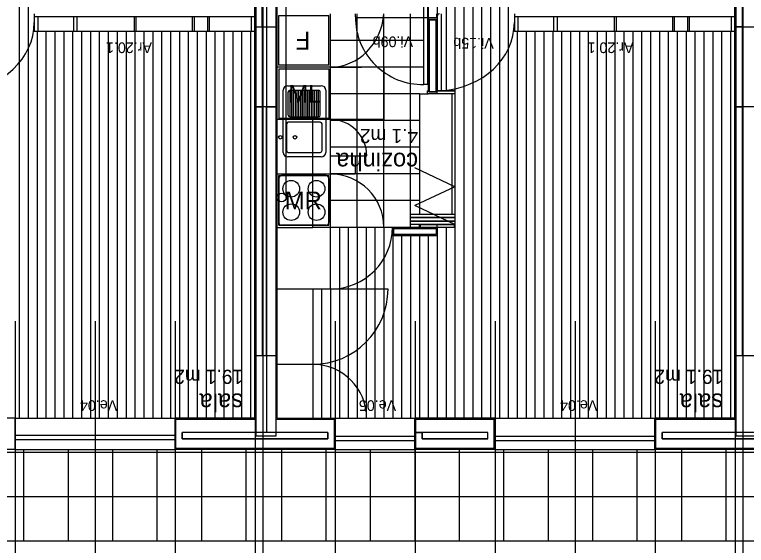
# Model space of a CAD drawing. Extents: x 1248 to 1356, y -443 to -224.
# Drawn here: x 1326.49 to 1334.72, y -248 to -242.03 of the extents above; entities that cross this region are included whole.
import ezdxf

# ---------------------------------------------------------------- set-up
doc = ezdxf.new("R2010")
doc.units = 0
for name, color, linetype in [('corte', 7, 'Continuous'), ('estereoctomias', 7, 'Continuous'), ('Level 1', 7, 'Continuous'), ('Level 10', 7, 'Continuous'), ('Level 11', 7, 'Continuous'), ('Level 13', 7, 'Continuous'), ('Level 2', 7, 'Continuous'), ('Level 3', 7, 'Continuous'), ('Level 4', 7, 'Continuous'), ('Level 40', 7, 'Continuous'), ('Level 60', 7, 'Continuous'), ('mob-fixo', 7, 'Continuous'), ('revestimentos', 7, 'Continuous'), ('vermelhos-cont', 7, 'Continuous'), ('vermelhos-tracej', 7, 'Continuous')]:
    doc.layers.add(name, color=color, linetype=linetype)

msp = doc.modelspace()

# ---------------------------------------------------------------- linework, layer by layer
at = {"layer": 'corte'}
for p, q in [((1331.1475, -242.892), (1331.1475, -242.902)), ((1331.2375, -242.892), (1331.2375, -242.924)), ((1328.304, -246.584), (1329.2018, -246.584)), ((1333.7025, -246.584), (1334.6025, -246.584)), ((1330.0125, -246.734), (1328.374, -246.734)), ((1331.8125, -246.734), (1331.0725, -246.734)), ((1335.414, -246.734), (1333.7725, -246.734)), ((1330.0125, -246.804), (1328.374, -246.804)), ((1331.8125, -246.804), (1331.0725, -246.804)), ((1335.414, -246.804), (1333.7725, -246.804)), ((1330.0825, -246.914), (1328.304, -246.914)), ((1331.8825, -246.914), (1331.0025, -246.914)), ((1335.484, -246.914), (1333.7025, -246.914))]:
    msp.add_line(p, q, dxfattribs=at)
for points in [[(1329.4318, -243.0713), (1329.2018, -243.0713), (1329.2018, -242.1713), (1329.4318, -242.1713)], [(1334.8325, -243.0713), (1334.6025, -243.0713), (1334.6025, -242.1713), (1334.8325, -242.1713)], [(1329.4318, -245.8713), (1329.2018, -245.8713), (1329.2018, -246.7713), (1329.4318, -246.7713)], [(1334.8325, -245.8713), (1334.6025, -245.8713), (1334.6025, -246.7713), (1334.8325, -246.7713)]]:
    msp.add_lwpolyline(points, close=True, dxfattribs=at)
at = {"layer": 'estereoctomias'}
for points in [[(1326.0268, -240.354), (1326.0268, -240.424), (1329.2018, -240.424), (1329.2018, -242.1713), (1329.2718, -242.1713), (1329.2718, -240.354), (1326.0268, -240.354)], [(1329.3225, -242.1713), (1329.4318, -242.1713), (1329.4325, -240.754), (1330.3525, -240.754), (1330.3525, -241.264), (1330.4875, -241.264), (1330.4875, -240.304), (1330.4325, -240.304), (1330.4325, -240.604), (1329.4325, -240.604), (1329.4325, -240.304), (1329.3225, -240.304)], [(1334.6725, -240.354), (1334.6725, -242.1713), (1334.6025, -242.1713), (1334.6025, -240.424), (1331.4125, -240.424), (1331.4125, -240.354)], [(1331.2275, -242.094), (1331.2275, -242.902), (1331.1575, -242.902), (1331.1575, -242.094)], [(1331.4425, -242.892), (1331.4425, -242.924), (1331.1325, -242.924), (1331.1325, -242.892), (1331.1475, -242.892), (1331.1475, -242.902), (1331.2375, -242.902), (1331.2375, -242.892), (1331.4425, -242.892)], [(1329.2718, -245.8713), (1329.2018, -245.8713), (1329.2018, -243.0713), (1329.2718, -243.0713)], [(1329.4318, -245.8713), (1329.3225, -245.8713), (1329.3225, -243.0713), (1329.4325, -243.0713), (1329.4325, -245.8713)], [(1334.6725, -245.8713), (1334.6025, -245.8713), (1334.6025, -243.0713), (1334.6725, -243.0713)], [(1331.2325, -244.4379), (1331.2325, -244.5079), (1330.7525, -244.5079), (1330.7525, -244.4379)], [(1331.4425, -244.3959), (1331.4425, -244.4279), (1331.0425, -244.4279), (1331.0425, -244.3959)], [(1329.4325, -246.584), (1330.0825, -246.584), (1330.0825, -246.914), (1328.304, -246.914), (1328.304, -246.584), (1329.2018, -246.584), (1329.2018, -246.734), (1328.374, -246.734), (1328.374, -246.804), (1330.0125, -246.804), (1330.0125, -246.734), (1329.4318, -246.734)], [(1331.8825, -246.584), (1331.8825, -246.914), (1331.0025, -246.914), (1331.0025, -246.734), (1331.0725, -246.734), (1331.0725, -246.804), (1331.8125, -246.804), (1331.8125, -246.734), (1331.0025, -246.734), (1331.0025, -246.584)], [(1334.8333, -246.584), (1335.484, -246.584), (1335.484, -246.914), (1333.7025, -246.914), (1333.7025, -246.584), (1334.6025, -246.584), (1334.6025, -246.734), (1333.7725, -246.734), (1333.7725, -246.804), (1335.414, -246.804), (1335.414, -246.734), (1334.8325, -246.734)]]:
    msp.add_lwpolyline(points, close=True, dxfattribs=at)
at = {"layer": 'Level 1'}
for p, q in [((1329.2718, -240.354), (1329.2718, -245.8713)), ((1329.3225, -240.304), (1329.3225, -246.734)), ((1334.6725, -240.354), (1334.6725, -245.8713)), ((1329.2018, -240.424), (1329.2018, -246.584)), ((1329.2018, -246.584), (1329.2018, -240.424)), ((1334.6025, -240.424), (1334.6025, -246.584)), ((1334.6025, -246.584), (1334.6025, -240.424)), ((1329.4325, -246.584), (1329.4325, -241.934)), ((1331.1575, -242.902), (1331.1575, -242.094)), ((1331.1575, -242.094), (1331.2275, -242.094)), ((1331.2275, -242.094), (1331.2275, -242.902)), ((1331.1475, -242.892), (1331.1325, -242.892)), ((1331.1325, -242.924), (1331.1325, -242.892)), ((1331.1475, -242.902), (1331.2375, -242.902)), ((1331.4425, -242.892), (1331.2375, -242.892)), ((1331.4425, -242.892), (1331.4425, -242.924)), ((1331.4425, -242.924), (1331.1325, -242.924)), ((1331.2325, -244.4379), (1330.7525, -244.4379)), ((1330.7525, -244.4379), (1330.7525, -244.5079)), ((1331.0425, -244.3959), (1331.0425, -244.424)), ((1331.4425, -244.3959), (1331.0425, -244.3959)), ((1331.0425, -244.3959), (1331.0425, -244.4279)), ((1331.0525, -244.3959), (1331.0525, -244.4279)), ((1331.2325, -244.4379), (1331.2325, -244.5079)), ((1331.2425, -244.4279), (1331.2425, -244.3959)), ((1331.4425, -244.4279), (1331.2425, -244.4279)), ((1331.4325, -244.3959), (1331.4325, -244.4279)), ((1331.4425, -244.3959), (1331.4425, -244.4279)), ((1330.7525, -244.5079), (1331.2325, -244.5079)), ((1328.304, -246.914), (1328.304, -246.584)), ((1329.4325, -246.584), (1330.0825, -246.584)), ((1330.0825, -246.584), (1330.0825, -246.914)), ((1331.8825, -246.584), (1331.0025, -246.584)), ((1331.0025, -246.914), (1331.0025, -246.584)), ((1331.8825, -246.914), (1331.8825, -246.584)), ((1333.7025, -246.914), (1333.7025, -246.584)), ((1328.374, -246.804), (1328.374, -246.734)), ((1330.0125, -246.734), (1330.0125, -246.804)), ((1331.0725, -246.804), (1331.0725, -246.734)), ((1331.8125, -246.804), (1331.8125, -246.734)), ((1333.7725, -246.804), (1333.7725, -246.734))]:
    msp.add_line(p, q, dxfattribs=at)
at = {"layer": 'Level 10'}
for p, q in [((1331.1425, -240.424), (1331.1425, -242.892)), ((1331.2425, -240.424), (1331.2425, -242.892)), ((1331.4425, -240.434), (1331.4425, -242.892)), ((1331.5425, -240.434), (1331.5425, -246.574)), ((1331.6425, -240.434), (1331.6425, -246.574)), ((1331.7425, -240.434), (1331.7425, -246.574)), ((1331.8425, -240.434), (1331.8425, -246.574)), ((1331.9425, -240.434), (1331.9425, -246.574)), ((1332.0425, -240.434), (1332.0425, -246.574)), ((1326.5418, -240.439), (1326.5418, -246.574)), ((1326.6418, -240.439), (1326.6418, -246.574)), ((1331.3425, -240.439), (1331.3425, -242.892)), ((1330.3425, -244.428), (1330.3425, -242.024)), ((1330.6425, -244.428), (1330.6425, -242.024)), ((1330.9425, -244.428), (1330.9425, -242.024)), ((1326.7418, -242.224), (1326.7418, -246.574)), ((1326.8418, -242.224), (1326.8418, -246.574)), ((1326.9418, -242.224), (1326.9418, -246.574)), ((1327.0418, -242.224), (1327.0418, -246.574)), ((1327.1418, -242.224), (1327.1418, -246.574)), ((1327.2418, -242.224), (1327.2418, -246.574)), ((1327.3418, -242.224), (1327.3418, -246.574)), ((1327.4418, -242.224), (1327.4418, -246.574)), ((1327.5418, -242.224), (1327.5418, -246.574)), ((1327.6418, -242.224), (1327.6418, -246.574)), ((1327.7418, -242.224), (1327.7418, -246.574)), ((1327.8418, -242.224), (1327.8418, -246.574)), ((1327.9418, -242.224), (1327.9418, -246.574)), ((1328.0418, -242.224), (1328.0418, -246.574)), ((1328.1418, -242.224), (1328.1418, -246.574)), ((1328.2418, -242.224), (1328.2418, -246.574)), ((1328.3418, -242.224), (1328.3418, -246.574)), ((1328.4418, -242.224), (1328.4418, -246.574)), ((1328.5418, -242.224), (1328.5418, -246.574)), ((1328.6418, -242.224), (1328.6418, -246.574)), ((1328.7418, -242.224), (1328.7418, -246.574)), ((1328.8418, -242.224), (1328.8418, -246.574)), ((1328.9418, -242.224), (1328.9418, -246.574)), ((1329.0418, -242.224), (1329.0418, -246.574)), ((1329.1418, -242.224), (1329.1418, -246.574)), ((1332.1425, -242.224), (1332.1425, -246.574)), ((1332.2425, -242.224), (1332.2425, -246.574)), ((1332.3425, -242.224), (1332.3425, -246.574)), ((1332.4425, -242.224), (1332.4425, -246.574)), ((1332.5425, -242.224), (1332.5425, -246.574)), ((1332.6425, -242.224), (1332.6425, -246.574)), ((1332.7425, -242.224), (1332.7425, -246.574)), ((1332.8425, -242.224), (1332.8425, -246.574)), ((1332.9425, -242.224), (1332.9425, -246.574)), ((1333.0425, -242.224), (1333.0425, -246.574)), ((1333.1425, -242.224), (1333.1425, -246.574)), ((1333.2425, -242.224), (1333.2425, -246.574)), ((1333.3425, -242.224), (1333.3425, -246.574)), ((1333.4425, -242.224), (1333.4425, -246.574)), ((1333.5425, -242.224), (1333.5425, -246.574)), ((1333.6425, -242.224), (1333.6425, -246.574)), ((1333.7425, -242.224), (1333.7425, -246.574)), ((1333.8425, -242.224), (1333.8425, -246.574)), ((1333.9425, -242.224), (1333.9425, -246.574)), ((1334.0425, -242.224), (1334.0425, -246.574)), ((1334.1425, -242.224), (1334.1425, -246.574)), ((1334.2425, -242.224), (1334.2425, -246.574)), ((1334.3425, -242.224), (1334.3425, -246.574)), ((1334.4425, -242.224), (1334.4425, -246.574)), ((1334.5425, -242.224), (1334.5425, -246.574)), ((1331.0925, -242.324), (1330.0425, -242.324)), ((1331.0925, -242.624), (1330.0425, -242.624)), ((1331.0925, -242.624), (1330.0425, -242.624)), ((1331.0425, -242.924), (1330.0425, -242.924)), ((1331.0425, -243.224), (1330.0425, -243.224)), ((1331.0425, -243.224), (1330.0425, -243.224)), ((1331.0425, -243.524), (1330.0425, -243.524)), ((1331.0425, -243.824), (1330.0425, -243.824)), ((1331.0425, -244.124), (1330.0425, -244.124)), ((1330.7425, -244.428), (1330.0425, -244.428)), ((1330.1425, -244.428), (1330.1425, -246.574)), ((1330.2425, -244.428), (1330.2425, -246.574)), ((1330.3425, -244.428), (1330.3425, -246.574)), ((1330.4425, -244.428), (1330.4425, -246.574)), ((1330.5425, -244.428), (1330.5425, -246.574)), ((1330.6425, -244.428), (1330.6425, -246.574)), ((1331.3425, -244.4279), (1331.3425, -246.574)), ((1331.4425, -244.4279), (1331.4425, -246.574)), ((1330.7425, -244.5179), (1330.7425, -246.574)), ((1330.8425, -244.5179), (1330.8425, -246.574)), ((1330.9425, -244.5179), (1330.9425, -246.574)), ((1331.0425, -244.5179), (1331.0425, -246.574)), ((1331.1425, -244.5179), (1331.1425, -246.574)), ((1331.2425, -244.5179), (1331.2425, -246.574)), ((1329.9425, -245.121), (1329.9425, -246.574)), ((1330.0425, -245.121), (1330.0425, -246.574)), ((1326.5933, -247.954), (1326.5933, -246.924)), ((1327.0933, -247.954), (1327.0933, -246.924)), ((1327.5933, -247.954), (1327.5933, -246.924)), ((1328.0933, -247.954), (1328.0933, -246.924)), ((1328.5933, -247.954), (1328.5933, -246.924)), ((1329.0933, -247.954), (1329.0933, -246.924)), ((1329.4933, -247.954), (1329.4933, -246.924)), ((1329.9933, -247.954), (1329.9933, -246.924)), ((1330.4933, -247.954), (1330.4933, -246.924)), ((1330.9933, -247.954), (1330.9933, -246.924)), ((1331.4933, -247.954), (1331.4933, -246.924)), ((1331.9933, -247.954), (1331.9933, -246.924)), ((1332.4933, -247.954), (1332.4933, -246.924)), ((1332.9933, -247.954), (1332.9933, -246.924)), ((1333.4933, -247.954), (1333.4933, -246.924)), ((1333.9933, -247.954), (1333.9933, -246.924)), ((1334.4933, -247.954), (1334.4933, -246.924)), ((1323.8933, -246.954), (1329.2933, -246.954)), ((1329.2933, -246.954), (1334.6933, -246.954)), ((1334.6933, -246.954), (1340.0933, -246.954)), ((1323.8933, -247.454), (1329.2933, -247.454)), ((1329.2933, -247.454), (1334.6933, -247.454)), ((1334.6933, -247.454), (1340.0933, -247.454)), ((1323.8933, -247.954), (1329.2933, -247.954)), ((1329.2933, -247.954), (1334.6933, -247.954)), ((1334.6933, -247.954), (1340.0933, -247.954))]:
    msp.add_line(p, q, dxfattribs=at)
at = {"layer": 'Level 11'}
for p, q in [((1329.4625, -242.604), (1329.4625, -242.044)), ((1329.4625, -242.044), (1330.0225, -242.044)), ((1330.0225, -242.604), (1330.0225, -242.044)), ((1330.0225, -242.604), (1329.4625, -242.604)), ((1329.5676, -243.1651), (1329.5676, -242.9035)), ((1329.5876, -242.8835), (1329.9076, -242.8835)), ((1329.5876, -243.1851), (1329.5876, -242.8835)), ((1329.6076, -243.1851), (1329.6076, -242.8835)), ((1329.6276, -243.1851), (1329.6276, -242.8835)), ((1329.6476, -243.1851), (1329.6476, -242.8835)), ((1329.6676, -243.1851), (1329.6676, -242.8835)), ((1329.6876, -243.1851), (1329.6876, -242.8835)), ((1329.7076, -243.1851), (1329.7076, -242.8835)), ((1329.7276, -243.1851), (1329.7276, -242.8835)), ((1329.7476, -243.1851), (1329.7476, -242.8835)), ((1329.7676, -243.1851), (1329.7676, -242.8835)), ((1329.7876, -243.1851), (1329.7876, -242.8835)), ((1329.8076, -243.1851), (1329.8076, -242.8835)), ((1329.8276, -243.1851), (1329.8276, -242.8835)), ((1329.8476, -243.1851), (1329.8476, -242.8835)), ((1329.8676, -243.1851), (1329.8676, -242.8835)), ((1329.8876, -243.1851), (1329.8876, -242.8835)), ((1329.9076, -243.1851), (1329.9076, -242.8835)), ((1329.9276, -243.1651), (1329.9276, -242.9035)), ((1329.5876, -243.1851), (1329.9076, -243.1851)), ((1329.5476, -243.2635), (1329.5476, -243.5635)), ((1329.9276, -243.2435), (1329.5676, -243.2435)), ((1329.9476, -243.5635), (1329.9476, -243.2635)), ((1329.5676, -243.5835), (1329.9276, -243.5835)), ((1329.4626, -243.874), (1329.4626, -244.374)), ((1329.9926, -243.844), (1329.4926, -243.844)), ((1330.0226, -243.874), (1330.0226, -244.374)), ((1329.9926, -244.404), (1329.4926, -244.404))]:
    msp.add_line(p, q, dxfattribs=at)
for points in [[(1329.5098, -243.5847), (1329.5098, -242.8833)], [(1329.5598, -242.8333), (1329.9382, -242.8333)], [(1329.9882, -242.8833), (1329.9882, -243.5847)], [(1329.9382, -243.6347), (1329.5598, -243.6347)]]:
    msp.add_lwpolyline(points, dxfattribs=at)
for centre, radius in [((1329.4777, -243.4135), 0.0199), ((1329.6436, -243.4135), 0.0199), ((1329.6, -243.9919), 0.0936), ((1329.8852, -243.9919), 0.0936), ((1329.6, -244.2561), 0.0936), ((1329.8852, -244.2561), 0.0936)]:
    msp.add_circle(centre, radius, dxfattribs=at)
for centre, radius, start, end in [((1329.5598, -242.8833), 0.05, 90, 180), ((1329.5876, -242.9035), 0.02, 90, 180), ((1329.9076, -242.9035), 0.02, 0, 90), ((1329.9382, -242.8833), 0.05, 0, 90), ((1329.5876, -243.1651), 0.02, 180, 270), ((1329.9076, -243.1651), 0.02, 270, 0), ((1329.5676, -243.2635), 0.02, 90, 180), ((1329.9276, -243.2635), 0.02, 0, 90), ((1329.5676, -243.5635), 0.02, 180, 270), ((1329.9276, -243.5635), 0.02, 270, 0), ((1329.5598, -243.5847), 0.05, 180, 270), ((1329.9382, -243.5847), 0.05, 270, 0), ((1329.4926, -243.874), 0.03, 89.99985, 180.0002), ((1329.9926, -243.874), 0.03, 0.00009, 90.0001), ((1329.4926, -244.374), 0.03, 180.00021, 269.99999), ((1329.9926, -244.374), 0.03, 270.00005, 0.00002)]:
    msp.add_arc(centre, radius, start, end, dxfattribs=at)
at = {"layer": 'Level 13'}
for p, q in [((1331.0925, -242.819), (1331.0925, -241.924)), ((1331.1375, -242.819), (1331.1375, -241.924)), ((1331.1375, -242.819), (1331.1375, -241.924)), ((1331.1375, -242.819), (1331.1375, -241.924)), ((1326.7098, -242.024), (1326.7098, -242.224)), ((1326.7098, -242.054), (1329.1918, -242.054)), ((1326.7498, -242.054), (1326.7498, -242.224)), ((1327.1498, -242.054), (1327.1498, -242.224)), ((1327.1898, -242.054), (1327.1898, -242.224)), ((1327.8338, -242.054), (1327.8338, -242.224)), ((1327.8538, -242.054), (1327.8538, -242.224)), ((1328.4878, -242.054), (1328.4878, -242.224)), ((1328.5078, -242.054), (1328.5078, -242.224)), ((1328.6578, -242.054), (1328.6578, -242.224)), ((1328.6778, -242.054), (1328.6778, -242.224)), ((1329.1518, -242.224), (1329.1518, -242.054)), ((1330.0425, -245.121), (1330.0425, -242.024)), ((1331.2475, -242.8898), (1331.2475, -242.044)), ((1331.2925, -242.8898), (1331.2925, -242.024)), ((1332.1105, -242.024), (1332.1105, -242.224)), ((1332.1105, -242.054), (1334.5925, -242.054)), ((1332.1505, -242.054), (1332.1505, -242.224)), ((1332.5505, -242.054), (1332.5505, -242.224)), ((1332.5905, -242.054), (1332.5905, -242.224)), ((1333.2345, -242.054), (1333.2345, -242.224)), ((1333.2545, -242.054), (1333.2545, -242.224)), ((1333.8885, -242.054), (1333.8885, -242.224)), ((1333.9085, -242.054), (1333.9085, -242.224)), ((1334.0585, -242.054), (1334.0585, -242.224)), ((1334.0785, -242.054), (1334.0785, -242.224)), ((1334.5525, -242.224), (1334.5525, -242.054)), ((1329.1918, -242.224), (1326.7098, -242.224)), ((1334.5925, -242.224), (1332.1105, -242.224)), ((1330.0425, -242.624), (1329.4425, -242.624)), ((1331.1375, -242.819), (1331.0925, -242.819)), ((1331.2925, -242.8898), (1331.2475, -242.8898)), ((1331.4425, -244.2809), (1330.9425, -244.2809)), ((1330.9425, -244.3159), (1330.9425, -244.2809)), ((1331.4425, -244.3159), (1330.9425, -244.3159)), ((1331.4425, -244.3209), (1330.9425, -244.3209)), ((1330.9425, -244.3559), (1330.9425, -244.3209)), ((1331.4425, -244.3559), (1330.9425, -244.3559)), ((1331.4425, -244.3609), (1330.9425, -244.3609)), ((1330.9425, -244.3959), (1330.9425, -244.3609)), ((1331.0425, -244.3959), (1330.9425, -244.3959)), ((1330.0425, -245.121), (1329.4425, -245.121)), ((1329.8425, -245.121), (1329.8425, -246.574))]:
    msp.add_line(p, q, dxfattribs=at)
msp.add_arc((1331.2675, -242.044), 0.02, 90, 180, dxfattribs=at)
at = {"layer": 'Level 2'}
for p, q in [((1331.0425, -242.924), (1331.0425, -244.2809)), ((1331.0425, -242.924), (1331.1425, -242.924)), ((1331.4425, -242.924), (1331.4425, -244.3959)), ((1331.0425, -244.3159), (1331.0425, -244.3209)), ((1331.0425, -244.3559), (1331.0425, -244.3609)), ((1326.494, -246.574), (1328.294, -246.574)), ((1330.0925, -246.574), (1330.9925, -246.574)), ((1331.8925, -246.574), (1333.6925, -246.574)), ((1326.494, -246.764), (1328.294, -246.764)), ((1330.0925, -246.774), (1330.9925, -246.774)), ((1331.8925, -246.774), (1333.6925, -246.774)), ((1326.494, -246.814), (1328.294, -246.814)), ((1330.0925, -246.824), (1330.9925, -246.824)), ((1331.8925, -246.824), (1333.6925, -246.824)), ((1326.494, -246.924), (1328.294, -246.924)), ((1330.0925, -246.924), (1330.9925, -246.924)), ((1331.8925, -246.924), (1333.6925, -246.924))]:
    msp.add_line(p, q, dxfattribs=at)
at = {"layer": 'Level 3'}
for p, q in [((1330.0425, -243.214), (1329.4425, -243.214)), ((1329.8425, -244.424), (1329.8425, -243.214)), ((1329.8425, -244.424), (1330.0425, -244.424)), ((1329.8425, -245.968), (1329.4425, -245.968))]:
    msp.add_line(p, q, dxfattribs=at)
at = {"layer": 'Level 4'}
for p, q in [((1330.3225, -242.059), (1330.3225, -242.024)), ((1331.2375, -242.069), (1330.3225, -242.069)), ((1331.2375, -242.069), (1331.2375, -242.024)), ((1329.4625, -242.644), (1329.4625, -243.204)), ((1329.4625, -242.644), (1330.0225, -242.644)), ((1330.0225, -242.644), (1330.0225, -243.204)), ((1330.0425, -242.624), (1330.3925, -242.624)), ((1330.0425, -242.624), (1330.3925, -242.624)), ((1330.6425, -242.624), (1330.6425, -243.214)), ((1331.4075, -242.924), (1331.4075, -244.2809)), ((1330.0225, -243.204), (1329.4625, -243.204)), ((1330.6425, -243.214), (1330.0425, -243.214)), ((1330.0425, -243.622), (1330.4505, -243.622)), ((1330.32, -243.622), (1330.32, -243.8263)), ((1331.4425, -243.9691), (1330.9903, -243.7557)), ((1329.4425, -243.824), (1330.0425, -243.8263)), ((1329.4625, -243.844), (1330.0225, -243.844)), ((1329.4625, -244.404), (1329.4625, -243.844)), ((1330.0225, -244.404), (1330.0225, -243.844)), ((1330.0425, -243.8263), (1330.32, -243.8263)), ((1331.4425, -243.9691), (1330.9903, -244.1825)), ((1331.4425, -244.3959), (1330.9903, -244.1825)), ((1329.4425, -244.428), (1329.8425, -244.428)), ((1329.4625, -244.404), (1330.0225, -244.404)), ((1330.6895, -245.121), (1329.8425, -245.121))]:
    msp.add_line(p, q, dxfattribs=at)
for centre, radius, start, end in [((1331.0767, -242.0652), 0.7542, 179.52968, 271.19857), ((1330.0425, -243.622), 0.408, 0, 90), ((1330.0425, -244.4263), 0.6, 0.2225, 90), ((1330.0425, -244.424), 0.697, 270, 0), ((1329.8425, -245.121), 0.847, 270, 0), ((1329.8425, -246.574), 0.606, 0, 90)]:
    msp.add_arc(centre, radius, start, end, dxfattribs=at)
for centre, major_axis, ratio, start_param, end_param in [((1330.0425, -241.9731), (0, -0.6509), 0.924693, 0, 1.492592), ((1325.8264, -242.124), (-0.8834, 0), 0.869287, 1.644887, 3.141577), ((1331.2271, -242.124), (-0.8834, 0), 0.869287, 1.644887, 3.141577)]:
    msp.add_ellipse(centre, major_axis=major_axis, ratio=ratio, start_param=start_param, end_param=end_param, dxfattribs=at)
at = {"layer": 'mob-fixo'}
for p, q in [((1329.4425, -244.091), (1329.4425, -240.604)), ((1329.5425, -244.091), (1329.5425, -240.604))]:
    msp.add_line(p, q, dxfattribs=at)
msp.add_circle((1329.4925, -244.091), 0.05, dxfattribs=at)
at = {"layer": 'revestimentos'}
for p, q in [((1329.1918, -246.574), (1329.1918, -240.424)), ((1329.1918, -246.574), (1329.1918, -240.424)), ((1334.5925, -246.574), (1334.5925, -240.424)), ((1334.5925, -246.574), (1334.5925, -240.434)), ((1329.4425, -246.574), (1329.4425, -242.024)), ((1331.1475, -242.902), (1331.1475, -242.084)), ((1331.1475, -242.084), (1331.2375, -242.084)), ((1331.2375, -242.084), (1331.2375, -242.892)), ((1331.2425, -244.4279), (1330.7425, -244.4279)), ((1330.7425, -244.4279), (1330.7425, -244.5179)), ((1331.2425, -244.4279), (1331.2425, -244.5179)), ((1330.7425, -244.5179), (1331.2425, -244.5179)), ((1326.494, -246.574), (1325.594, -246.574)), ((1326.494, -246.924), (1326.494, -246.574)), ((1329.1918, -246.574), (1328.294, -246.574)), ((1328.294, -246.924), (1328.294, -246.574)), ((1329.4425, -246.574), (1330.0925, -246.574)), ((1330.0925, -246.574), (1330.0925, -246.924)), ((1330.9925, -246.924), (1330.9925, -246.574)), ((1331.8925, -246.574), (1330.9925, -246.574)), ((1331.8925, -246.924), (1331.8925, -246.574)), ((1334.5925, -246.574), (1333.6925, -246.574)), ((1333.6925, -246.924), (1333.6925, -246.574)), ((1326.494, -246.924), (1325.594, -246.924)), ((1330.0925, -246.924), (1328.294, -246.924)), ((1331.8925, -246.924), (1330.9925, -246.924)), ((1335.494, -246.924), (1333.6925, -246.924))]:
    msp.add_line(p, q, dxfattribs=at)
at = {"layer": 'vermelhos-cont'}
for p, q in [((1329.284, -250.7923), (1329.284, -229.6198)), ((1334.684, -250.7923), (1334.684, -229.6198))]:
    msp.add_line(p, q, dxfattribs=at)
at = {"layer": 'vermelhos-tracej'}
for p, q in [((1326.494, -245.4838), (1326.494, -250.4459)), ((1327.394, -245.4838), (1327.394, -250.4459)), ((1328.294, -245.4838), (1328.294, -250.4459)), ((1329.194, -245.4838), (1329.194, -250.4459)), ((1330.094, -245.4838), (1330.094, -250.4459)), ((1330.994, -245.4838), (1330.994, -250.4459)), ((1331.894, -245.4838), (1331.894, -250.4459)), ((1332.794, -245.4838), (1332.794, -250.4459)), ((1333.694, -245.4838), (1333.694, -250.4459)), ((1334.594, -245.4838), (1334.594, -250.4459))]:
    msp.add_line(p, q, dxfattribs=at)

# ---------------------------------------------------------------- texts
at = {"layer": 'Level 11'}
msp.add_text('F', height=0.2, rotation=180, dxfattribs=at).set_placement((1329.814, -242.2263))
for s, p in [('ML', (1329.5686, -243.024)), ('MR', (1329.5288, -244.224))]:
    msp.add_text(s, height=0.2, dxfattribs=at).set_placement(p)
at = {"layer": 'Level 40'}
for s, p in [('Vi.09b', (1330.972, -242.2797)), ('Vi.15b', (1331.8786, -242.295)), ('Ar.20.1', (1328.0337, -242.3462)), ('Ar.20.1', (1333.4509, -242.3462)), ('Ve.04', (1327.6431, -246.3717)), ('Ve.05', (1330.7805, -246.3717)), ('Ve.04', (1333.0438, -246.3717))]:
    msp.add_text(s, height=0.12, rotation=180.00001, dxfattribs=at).set_placement(p)
at = {"layer": 'Level 60'}
for s, height, p in [('4.1 m2', 0.16, (1331.0274, -243.3196)), ('cozinha', 0.2, (1331.0274, -243.5874)), ('19.1 m2', 0.16, (1329.0584, -246.0279)), ('19.1 m2', 0.16, (1334.4592, -246.0279)), ('sala', 0.2, (1329.0584, -246.2957)), ('sala', 0.2, (1334.4592, -246.2957))]:
    msp.add_text(s, height=height, rotation=180, dxfattribs=at).set_placement(p)

doc.saveas('drawing.dxf')
